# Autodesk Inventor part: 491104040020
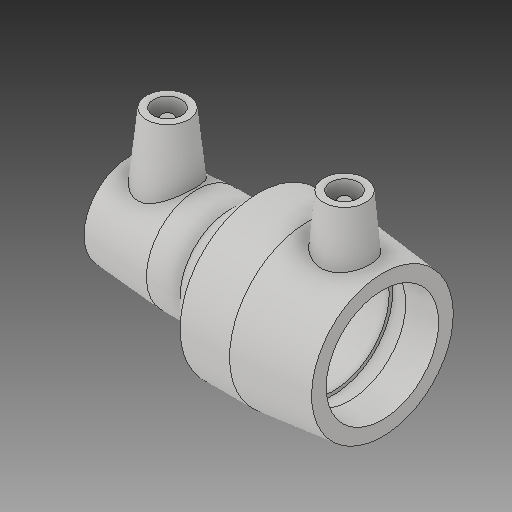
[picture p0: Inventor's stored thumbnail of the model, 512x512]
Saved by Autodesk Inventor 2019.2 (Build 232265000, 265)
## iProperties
Created: 2017-06
Part Number: 491104040020
Material: Generic
Description: PLASSON REDUCING COUPLER 40-20
Document SubType Name: Modeling
Designer: KIM
Mass: 54.8237 g
Surface Area: 155.252 cm^2
Volume: 54.8237 cm^3
Density: 1 g/cm^3
Appearance: Default
Author: KIM
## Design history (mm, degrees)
derived "491104.ipt"
feature "Solid1::491104.ipt"
tag "TaggingFeature1"
body "Solid1"
other parameters: "d2" = 36, "d4" = 24, "d5" = 32.4, "d8" = 168 deg, "d10" = 16, "d11" = 5.33333, "d14" = 17.6296, "d19" = 2, "d20" = 168 deg, "d22" = 108.92847, "d25" = 135 deg, "d29" = 38, "d30" = 15, "d31" = 31.5, "d34" = 6 deg, "d35" = 15, "d38" = 27, "d39" = 5 deg, "d41" = 4, "d42" = 14, "d43" = 0, "d45" = 4, "d46" = 14, "d47" = 0, "d48" = 36, "d50" = 56, "d52" = 18, "d53" = 17.6, "d54" = 5.86667, "d55" = 168 deg, "d56" = 26.4, "d57" = 44, "d58" = 50.4, "d59" = 2, "d60" = 135 deg, "d61" = 44, "d62" = 15, "d64" = 4, "d66" = 5 deg, "d67" = 14, "d68" = 0, "d69" = 31.5, "d70" = 36, "d71" = 56, "d73" = 52.64, "d76" = 2, "d77" = 168 deg, "d79" = 2, "d80" = 44, "d81" = 18, "d82" = 33.84, "d83" = 120 deg, "d88" = 15, "d89" = 22, "d90" = 5 deg, "d92" = 4, "d93" = 14, "d94" = 0, "d95" = 3, "d96" = 0, "d97" = 3, "d98" = 0, "d99" = 11.6, "d100" = 2.9, "d101" = 32.8248, "d102" = 20 deg, "d103" = 12.76, "d104" = 3.19, "d105" = 51.0608, "d106" = 3.60705, "d107" = 3, "d108" = 0, "d109" = 3, "d110" = 0, "D_1" = 36, "A_1" = 38, "d_2" = 12, "L_1" = 44, "A_" = 44, "D_" = 56
